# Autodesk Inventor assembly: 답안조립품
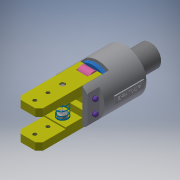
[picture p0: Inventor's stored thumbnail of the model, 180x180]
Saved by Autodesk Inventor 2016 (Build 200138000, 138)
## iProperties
Created: 2019-02
Part Number: 답안조립품
Material: 일반
Document SubType Name: Assembly
Designer: 605-12
Author: 605-12
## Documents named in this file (11)
- C:\Users\605-12\Desktop\490207V1010\490207V1010\답안조립품.iam
- C:\Users\605-12\Desktop\490207V1010\490207V1010\본체.ipt
- C:\Users\605-12\Desktop\490207V1010\490207V1010\O-링.ipt
- C:\Users\605-12\Desktop\490207V1010\490207V1010\피스톤.ipt
- C:\Users\605-12\Desktop\490207V1010\490207V1010\부시.ipt
- C:\Users\605-12\Desktop\490207V1010\490207V1010\평행핀 6x28.ipt
- C:\Users\605-12\Desktop\490207V1010\490207V1010\핀.ipt
- C:\Users\605-12\Desktop\490207V1010\490207V1010\핑거.ipt
- C:\Users\605-12\Desktop\490207V1010\490207V1010\E-링.ipt
- C:\Users\605-12\Desktop\490207V1010\490207V1010\가이드핀.ipt
- C:\Users\605-12\Desktop\490207V1010\490207V1010\스프링.ipt
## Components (11 placed, 6 different names)
1. O-링:1
2. O-링:2
3. 피스톤:1
4. 핀:1
5. 핀:2
6. 핑거:1
7. 핑거:2
8. E-링:1
9. E-링:2
10. 가이드핀:1
11. 가이드핀:2
